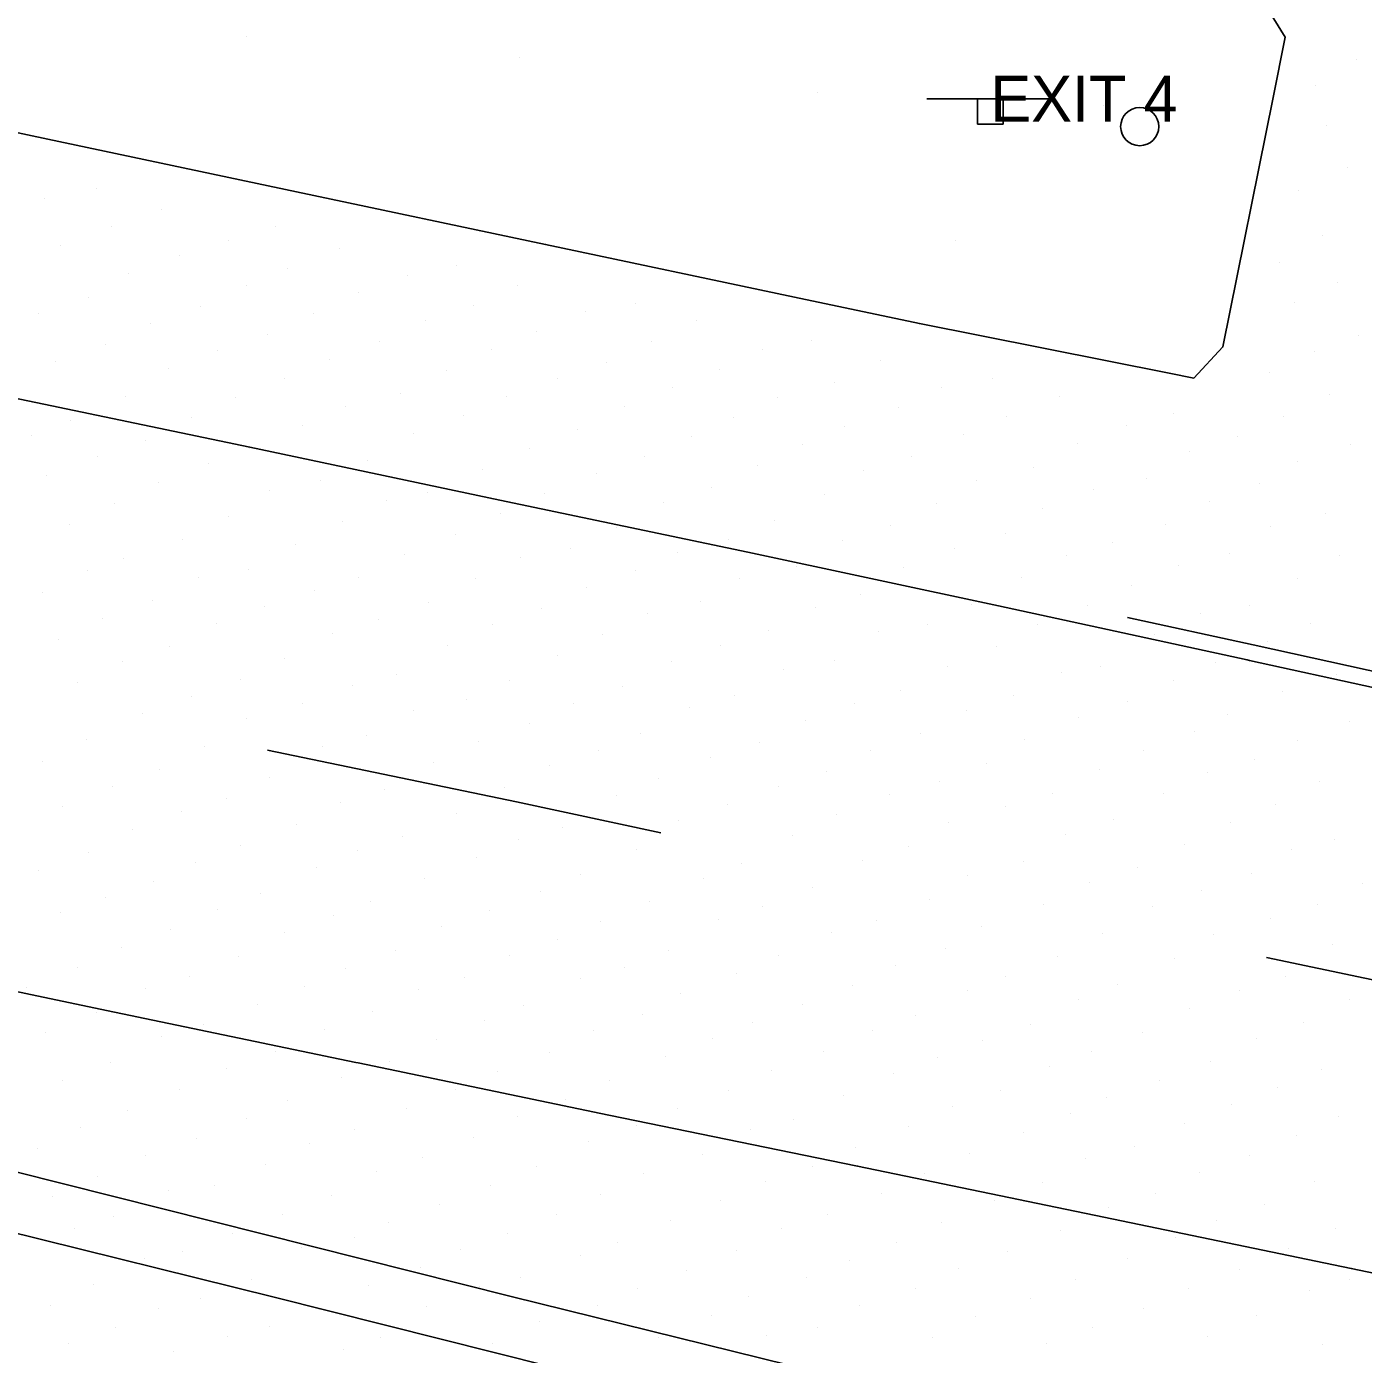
# Model space of a CAD drawing. Extents: x 1732346 to 1733076, y 467730 to 468633.
# Drawn here: x 1732773.5 to 1732826.1, y 468037.8 to 468090 of the extents above; entities that cross this region are included whole.
import ezdxf

# ---------------------------------------------------------------- set-up
doc = ezdxf.new("R2010")
doc.units = 0
for name, color, linetype in [('Default', 7, 'Continuous'), ('S_Ground_SpotElevation', 7, 'Continuous'), ('S_Guardrail_Beam', 7, 'Continuous'), ('S_Roadway_Edge_Pavement', 7, 'Continuous'), ('S_Roadway_Painted_Lines', 7, 'Continuous'), ('S_Text', 7, 'Continuous'), ('S_Traffic_Posts', 7, 'Continuous'), ('S_Traffic_Sign_SinglePost', 7, 'Continuous')]:
    doc.layers.add(name, color=color, linetype=linetype)

# ---------------------------------------------------------------- blocks, each defined once
blk = doc.blocks.new('POINT_DISPLAY')
at = {"layer": 'Default'}
blk.add_line((0, 0), (0, 0), dxfattribs=at)

msp = doc.modelspace()

# ---------------------------------------------------------------- linework, layer by layer
at = {"layer": 'S_Guardrail_Beam'}
for points in [[(1733057.134, 467971.295), (1733035.513, 467976.813), (1732996.091, 467986.731), (1732979.891, 467990.788), (1732924.503, 468005.981), (1732878.605, 468018.398), (1732839.517, 468028.474), (1732792.578, 468040.072), (1732765.198, 468046.962), (1732740.636, 468052.31), (1732695.156, 468062.036), (1732651.207, 468071.306), (1732593.235, 468083.607), (1732548.761, 468092.759), (1732525.66, 468097.849), (1732480.631, 468107.455), (1732450.278, 468113.819)], [(1732601.211, 468079.491), (1732624.681, 468074.488), (1732647.285, 468069.707), (1732677.097, 468063.407), (1732688.033, 468061.183), (1732704.968, 468057.509), (1732745.244, 468048.961), (1732757.76, 468046.26), (1732765.606, 468044.404), (1732772.588, 468042.691), (1732783.275, 468040.038), (1732800.615, 468035.672), (1732820.179, 468030.871), (1732839.038, 468026.193)]]:
    msp.add_lwpolyline(points, dxfattribs=at)
at = {"layer": 'S_Roadway_Edge_Pavement'}
msp.add_lwpolyline([(1732745.022, 468091.776), (1732754.805, 468089.704), (1732764.588, 468087.632), (1732774.371, 468085.56), (1732784.154, 468083.488), (1732793.937, 468081.416), (1732803.719, 468079.344), (1732808.631, 468078.304), (1732818.44, 468076.359), (1732819.413, 468076.166), (1732820.557, 468077.392), (1732822.529, 468087.196), (1732823.007, 468089.57), (1732821.659, 468091.736)], dxfattribs=at)
at = {"layer": 'S_Roadway_Painted_Lines'}
for points in [[(1732674.928, 468096.211), (1732684.719, 468094.102), (1732694.509, 468091.966), (1732704.231, 468089.834), (1732713.923, 468087.737), (1732723.729, 468085.628), (1732733.386, 468083.606), (1732743.244, 468081.582), (1732753.103, 468079.541), (1732762.798, 468077.529), (1732772.584, 468075.483), (1732772.711, 468075.456), (1732782.31, 468073.445), (1732792.144, 468071.365), (1732801.882, 468069.322), (1732811.732, 468067.208), (1732821.504, 468065.09), (1732821.605, 468065.069), (1732831.424, 468062.914)], [(1732669.338, 468074.084), (1732679.154, 468072.013), (1732688.927, 468069.949), (1732698.566, 468067.924), (1732708.376, 468065.853), (1732717.963, 468063.798), (1732727.768, 468061.722), (1732737.582, 468059.646), (1732747.326, 468057.582), (1732757.134, 468055.483), (1732766.913, 468053.366), (1732776.686, 468051.303), (1732786.474, 468049.265), (1732786.574, 468049.244), (1732796.428, 468047.189), (1732806.197, 468045.195), (1732815.879, 468043.181), (1732825.596, 468041.169), (1732835.331, 468039.133)], [(1732816.801, 468066.748), (1732821.738, 468065.678), (1732831.556, 468063.524), (1732841.335, 468061.437), (1732841.488, 468061.404), (1732851.348, 468059.327), (1732861.184, 468057.266), (1732870.85, 468055.293), (1732880.627, 468053.214), (1732890.392, 468051.101), (1732900.141, 468048.932), (1732909.856, 468046.816), (1732919.69, 468044.654), (1732928.671, 468042.737), (1732938.42, 468040.774), (1732947.936, 468038.748), (1732952.222, 468037.835)], [(1732783.004, 468061.533), (1732792.794, 468059.505), (1732798.466, 468058.296)], [(1732822.262, 468053.388), (1732832.047, 468051.334), (1732837.132, 468050.246)]]:
    msp.add_lwpolyline(points, dxfattribs=at)
at = {"layer": 'S_Traffic_Posts'}
msp.add_circle((1732817.284, 468086.048), 0.749, dxfattribs=at)
at = {"layer": 'S_Traffic_Sign_SinglePost'}
msp.add_line((1732808.92, 468087.145), (1732813.91, 468087.145), dxfattribs=at)
msp.add_lwpolyline([(1732810.916, 468087.145), (1732811.914, 468087.145), (1732811.914, 468086.147), (1732810.916, 468086.147)], close=True, dxfattribs=at)

# ---------------------------------------------------------------- block references
at = {"layer": 'S_Ground_SpotElevation'}
for p in [(1732782.169, 468089.575), (1732792.919, 468088.748), (1732825.81, 468088.678), (1732804.606, 468087.391), (1732824.182, 468087.646), (1732815.881, 468086.884), (1732824.634, 468086.108), (1732825.466, 468084.447), (1732774.263, 468083.23), (1732776.289, 468083.612), (1732823.517, 468083.553), (1732778.852, 468082.774), (1732776.89, 468082.113), (1732783.314, 468082.108), (1732781.47, 468081.576), (1732810.032, 468081.556), (1732824.476, 468081.759), (1732774.872, 468081.394), (1732785.851, 468081.24), (1732779.545, 468080.974), (1732790.423, 468080.599), (1732822.768, 468080.717), (1732777.54, 468080.282), (1732783.785, 468080.459), (1732788.525, 468080.188), (1732782.167, 468079.808), (1732786.58, 468079.533), (1732792.835, 468079.788), (1732825.047, 468079.91), (1732775.955, 468079.316), (1732780.372, 468078.958), (1732791.103, 468079.005), (1732797.487, 468079.093), (1732823.362, 468079.153), (1732774.023, 468078.686), (1732784.797, 468078.69), (1732789.206, 468078.415), (1732795.518, 468078.773), (1732799.867, 468078.435), (1732778.405, 468078.299), (1732793.594, 468078.004), (1732776.635, 468077.493), (1732783.024, 468077.862), (1732787.42, 468077.589), (1732798.112, 468077.618), (1732804.398, 468077.657), (1732825.887, 468077.823), (1732774.662, 468076.827), (1732781.039, 468077.262), (1732785.459, 468076.913), (1732791.813, 468077.271), (1732802.461, 468077.274), (1732807.107, 468076.87), (1732824.153, 468077.215), (1732779.129, 468076.546), (1732790.045, 468076.443), (1732796.339, 468076.795), (1732800.76, 468076.519), (1732822.395, 468076.395), (1732783.665, 468076.155), (1732794.403, 468076.151), (1732798.905, 468075.786), (1732805.308, 468075.999), (1732809.486, 468075.799), (1732811.487, 468076.139), (1732777.435, 468075.438), (1732781.738, 468075.403), (1732788.231, 468075.574), (1732792.404, 468075.431), (1732803.065, 468075.389), (1732814.116, 468075.449), (1732824.731, 468075.515), (1732786.073, 468075.057), (1732797.039, 468075.03), (1732807.798, 468074.997), (1732818.607, 468074.781), (1732775.28, 468074.494), (1732780.011, 468074.597), (1732784.371, 468074.301), (1732790.72, 468074.676), (1732801.329, 468074.614), (1732805.695, 468074.251), (1732812.038, 468074.67), (1732816.75, 468074.297), (1732822.931, 468074.652), (1732773.728, 468073.888), (1732778.22, 468073.705), (1732788.746, 468073.995), (1732795.209, 468074.147), (1732799.684, 468073.878), (1732810.349, 468073.93), (1732821.146, 468073.874), (1732782.295, 468073.399), (1732793.32, 468073.405), (1732804.021, 468073.539), (1732814.854, 468073.604), (1732819.235, 468073.267), (1732825.582, 468073.567), (1732776.326, 468073.08), (1732780.7, 468072.792), (1732786.92, 468072.917), (1732797.839, 468073.094), (1732802.28, 468072.739), (1732808.332, 468073.099), (1732813.129, 468072.631), (1732823.502, 468072.902), (1732774.324, 468072.333), (1732785.083, 468072.12), (1732791.443, 468072.581), (1732795.94, 468072.421), (1732806.442, 468072.523), (1732810.885, 468072.129), (1732817.552, 468072.229), (1732778.733, 468072.062), (1732783.09, 468071.76), (1732789.291, 468071.674), (1732793.908, 468071.646), (1732800.452, 468071.845), (1732804.912, 468071.595), (1732815.481, 468071.795), (1732821.991, 468072.016), (1732776.984, 468071.225), (1732787.695, 468071.372), (1732798.58, 468071.289), (1732809.307, 468071.253), (1732820.011, 468071.319), (1732781.495, 468070.742), (1732785.952, 468070.535), (1732792.166, 468070.823), (1732802.946, 468070.562), (1732813.449, 468071.037), (1732824.601, 468070.832), (1732775.224, 468070.391), (1732790.416, 468070.001), (1732796.719, 468070.276), (1732807.475, 468070.354), (1732812.015, 468070.065), (1732818.294, 468070.403), (1732822.442, 468070.32), (1732779.68, 468069.831), (1732784.116, 468069.608), (1732801.132, 468069.824), (1732805.59, 468069.774), (1732809.997, 468069.481), (1732816.223, 468069.711), (1732777.362, 468069.078), (1732788.405, 468069.245), (1732792.946, 468069.125), (1732794.9, 468069.448), (1732799.132, 468069.309), (1732814.406, 468069.177), (1732820.802, 468069.279), (1732825.13, 468069.206), (1732775.924, 468068.601), (1732782.265, 468068.652), (1732797.474, 468068.599), (1732803.804, 468068.74), (1732807.992, 468068.735), (1732818.795, 468068.783), (1732780.301, 468068.324), (1732786.569, 468068.316), (1732791.167, 468068.27), (1732795.55, 468067.95), (1732801.562, 468068.302), (1732812.639, 468068.345), (1732816.973, 468067.993), (1732823.474, 468068.283), (1732774.151, 468067.734), (1732778.482, 468067.417), (1732784.864, 468067.833), (1732800.043, 468067.387), (1732806.327, 468067.64), (1732782.886, 468067.172), (1732789.321, 468067.337), (1732793.781, 468067.127), (1732797.942, 468066.916), (1732804.532, 468067.15), (1732810.675, 468067.283), (1732815.22, 468067.225), (1732819.66, 468066.926), (1732821.604, 468067.206), (1732776.521, 468066.706), (1732781.001, 468066.535), (1732787.372, 468066.665), (1732791.869, 468066.495), (1732808.933, 468066.473), (1732813.255, 468066.483), (1732823.996, 468066.513), (1732774.795, 468065.89), (1732785.548, 468066.117), (1732796.187, 468066.098), (1732802.697, 468066.247), (1732807.002, 468066.199), (1732817.876, 468066.092), (1732822.318, 468065.798), (1732779.153, 468065.599), (1732790.096, 468065.642), (1732800.807, 468065.656), (1732811.641, 468065.62), (1732777.303, 468065.022), (1732783.679, 468065.145), (1732794.416, 468065.246), (1732798.887, 468065.025), (1732805.283, 468065.054), (1732809.734, 468064.809), (1732815.751, 468064.845), (1732820.261, 468065.001), (1732781.932, 468064.308), (1732788.086, 468064.52), (1732792.51, 468064.267), (1732803.292, 468064.709), (1732814.201, 468064.589), (1732818.63, 468064.276), (1732825.001, 468064.5), (1732775.558, 468064.193), (1732786.332, 468064.063), (1732796.975, 468064.041), (1732801.373, 468063.707), (1732807.885, 468063.882), (1732822.882, 468063.828), (1732780.019, 468063.646), (1732784.369, 468063.37), (1732790.834, 468063.539), (1732795.018, 468063.365), (1732799.573, 468063.215), (1732806.081, 468063.377), (1732812.333, 468063.672), (1732816.811, 468063.461), (1732778.107, 468062.999), (1732782.182, 468062.77), (1732788.759, 468063.095), (1732804.135, 468062.72), (1732810.488, 468063.11), (1732814.886, 468062.813), (1732820.717, 468062.923), (1732825.531, 468062.679), (1732786.894, 468062.135), (1732793.293, 468062.574), (1732797.658, 468062.212), (1732808.669, 468062.21), (1732819.433, 468062.265), (1732775.897, 468061.947), (1732780.532, 468061.665), (1732785.159, 468061.686), (1732791.315, 468061.869), (1732802.334, 468061.858), (1732812.748, 468061.946), (1732823.48, 468061.915), (1732774.155, 468061.084), (1732796.002, 468061.528), (1732800.431, 468061.237), (1732806.704, 468061.514), (1732817.422, 468061.546), (1732821.795, 468061.182), (1732778.777, 468060.767), (1732789.549, 468061.039), (1732794.109, 468060.927), (1732804.959, 468060.715), (1732811.247, 468061.029), (1732815.719, 468060.788), (1732819.961, 468060.659), (1732776.927, 468060.126), (1732783.106, 468060.475), (1732792.304, 468060.057), (1732798.365, 468060.442), (1732803.078, 468060.122), (1732809.417, 468060.304), (1732824.342, 468060.292), (1732781.379, 468059.625), (1732787.609, 468059.979), (1732796.735, 468059.768), (1732807.439, 468059.788), (1732813.866, 468059.846), (1732818.22, 468059.855), (1732774.938, 468059.342), (1732779.644, 468059.137), (1732785.862, 468059.489), (1732790.435, 468059.051), (1732801.079, 468059.4), (1732805.378, 468059.003), (1732812.002, 468059.324), (1732822.616, 468059.421), (1732784.133, 468058.637), (1732794.613, 468058.514), (1732799.148, 468058.756), (1732809.759, 468058.693), (1732816.257, 468058.813), (1732820.868, 468058.714), (1732777.712, 468058.412), (1732788.32, 468058.144), (1732792.868, 468058.038), (1732803.638, 468058.19), (1732814.373, 468058.231), (1732824.951, 468058.023), (1732775.963, 468057.532), (1732781.941, 468057.789), (1732786.534, 468057.603), (1732797.492, 468057.638), (1732808.218, 468057.748), (1732819.045, 468057.826), (1732823.248, 468057.645), (1732780.186, 468057.127), (1732784.934, 468056.918), (1732791.228, 468057.304), (1732801.639, 468057.081), (1732806.378, 468057.21), (1732812.728, 468057.174), (1732817.206, 468056.926), (1732774.023, 468056.801), (1732778.526, 468056.369), (1732789.195, 468056.503), (1732795.313, 468056.66), (1732800.142, 468056.508), (1732810.529, 468056.617), (1732815.317, 468056.343), (1732821.679, 468056.673), (1732782.729, 468055.921), (1732793.726, 468055.989), (1732804.44, 468056.152), (1732819.725, 468056.011), (1732826.056, 468056.312), (1732776.655, 468055.74), (1732781.031, 468055.296), (1732787.066, 468055.578), (1732798.028, 468055.605), (1732802.453, 468055.388), (1732809.005, 468055.683), (1732813.5, 468055.467), (1732817.802, 468055.388), (1732824.265, 468055.457), (1732774.87, 468055.17), (1732785.603, 468055.05), (1732791.72, 468055.219), (1732796.112, 468054.823), (1732800.713, 468054.887), (1732806.922, 468054.835), (1732822.411, 468054.918), (1732779.179, 468054.485), (1732783.684, 468054.367), (1732789.84, 468054.594), (1732805.187, 468054.358), (1732811.087, 468054.627), (1732815.842, 468054.333), (1732820.178, 468054.31), (1732777.269, 468053.773), (1732794.389, 468054.112), (1732809.635, 468053.746), (1732824.851, 468053.917), (1732781.874, 468053.442), (1732788.023, 468053.671), (1732792.528, 468053.482), (1732798.757, 468053.682), (1732803.082, 468053.477), (1732814.043, 468053.444), (1732818.653, 468053.366), (1732775.535, 468052.984), (1732786.063, 468052.952), (1732797.055, 468053.009), (1732801.443, 468052.748), (1732807.704, 468053.072), (1732773.556, 468052.199), (1732778.218, 468052.174), (1732779.928, 468052.626), (1732784.473, 468052.268), (1732788.957, 468052.138), (1732790.742, 468052.609), (1732795.32, 468052.548), (1732806.016, 468052.303), (1732812.013, 468052.653), (1732816.419, 468052.343), (1732823.033, 468052.655), (1732799.225, 468051.96), (1732810.512, 468052.091), (1732814.864, 468051.721), (1732821.202, 468052.091), (1732825.541, 468051.738), (1732776.301, 468051.211), (1732782.63, 468051.53), (1732787.138, 468051.272), (1732793.075, 468051.503), (1732797.73, 468051.155), (1732804.034, 468051.562), (1732808.482, 468051.104), (1732819.251, 468051.388), (1732780.486, 468050.742), (1732791.538, 468050.923), (1732802.065, 468050.835), (1732813.012, 468050.771), (1732823.741, 468050.828), (1732774.3, 468050.447), (1732778.849, 468050.279), (1732785.257, 468050.543), (1732789.639, 468050.157), (1732795.837, 468050.51), (1732800.504, 468050.195), (1732806.788, 468050.532), (1732811.114, 468050.136), (1732817.381, 468050.425), (1732821.87, 468050.215), (1732783.318, 468049.68), (1732794.075, 468049.663), (1732804.856, 468049.698), (1732815.408, 468049.707), (1732776.844, 468049.253), (1732781.4, 468049.043), (1732787.798, 468049.299), (1732798.633, 468049.484), (1732809.331, 468049.446), (1732813.749, 468049.118), (1732820.071, 468049.322), (1732774.941, 468048.541), (1732785.936, 468048.688), (1732792.063, 468048.922), (1732796.438, 468048.552), (1732802.821, 468048.938), (1732807.598, 468048.818), (1732818.052, 468048.55), (1732824.425, 468048.982), (1732779.544, 468048.185), (1732790.405, 468048.213), (1732801.109, 468048.177), (1732805.64, 468047.975), (1732811.831, 468048.154), (1732822.698, 468048.278), (1732783.814, 468047.786), (1732788.467, 468047.449), (1732794.731, 468047.792), (1732799.104, 468047.442), (1732809.943, 468047.544), (1732815.97, 468047.874), (1732820.886, 468047.619), (1732777.52, 468047.358), (1732782.174, 468047.064), (1732792.826, 468047.133), (1732803.665, 468047.013), (1732814.557, 468047.249), (1732825.116, 468047.156), (1732775.652, 468046.702), (1732786.431, 468046.615), (1732797.495, 468046.791), (1732801.978, 468046.629), (1732808.182, 468046.736), (1732812.712, 468046.52), (1732819.039, 468046.852), (1732823.459, 468046.413), (1732773.989, 468045.896), (1732780.203, 468046.291), (1732784.645, 468046.069), (1732791.105, 468046.313), (1732795.605, 468046.156), (1732806.111, 468045.939), (1732817.064, 468045.956), (1732778.224, 468045.589), (1732789.116, 468045.546), (1732800.108, 468045.661), (1732810.612, 468045.691), (1732815.151, 468045.502), (1732821.587, 468045.611), (1732782.935, 468045.236), (1732787.301, 468044.969), (1732793.566, 468045.159), (1732797.801, 468044.904), (1732804.417, 468045.191), (1732808.818, 468044.893), (1732819.637, 468044.926), (1732776.33, 468044.779), (1732780.931, 468044.435), (1732791.763, 468044.421), (1732802.56, 468044.6), (1732813.464, 468044.534), (1732824.153, 468044.599), (1732774.54, 468044.005), (1732779.113, 468044.221), (1732785.521, 468044.049), (1732796.082, 468044.084), (1732800.817, 468043.829), (1732807.14, 468044.126), (1732811.587, 468043.83), (1732817.887, 468044.125), (1732776.946, 468043.225), (1732783.594, 468043.308), (1732789.772, 468043.695), (1732794.36, 468043.298), (1732805.03, 468043.298), (1732816.067, 468043.571), (1732822.185, 468043.697), (1732775.42, 468042.725), (1732787.781, 468042.991), (1732798.844, 468043.069), (1732803.195, 468042.738), (1732809.48, 468042.992), (1732820.291, 468043.065), (1732824.994, 468042.723), (1732781.63, 468042.537), (1732786.43, 468042.395), (1732792.441, 468042.537), (1732796.767, 468042.204), (1732807.713, 468042.191), (1732814.183, 468042.643), (1732818.683, 468042.398), (1732779.678, 468041.833), (1732784.356, 468042.003), (1732790.598, 468041.928), (1732795.321, 468041.661), (1732801.455, 468041.872), (1732812.1, 468041.848), (1732823.116, 468041.954), (1732778.166, 468041.568), (1732789.007, 468041.215), (1732805.888, 468041.464), (1732810.166, 468041.184), (1732816.804, 468041.579), (1732821.193, 468041.13), (1732782.387, 468040.744), (1732792.936, 468040.804), (1732799.474, 468041.093), (1732804.18, 468040.794), (1732814.775, 468040.721), (1732825.547, 468040.753), (1732776.177, 468040.547), (1732786.983, 468040.498), (1732791.338, 468040.468), (1732797.56, 468040.4), (1732801.91, 468040.076), (1732808.478, 468040.382), (1732819.197, 468040.376), (1732823.957, 468040.298), (1732774.479, 468039.732), (1732778.737, 468039.608), (1732780.386, 468039.998), (1732785.026, 468039.558), (1732789.242, 468039.686), (1732795.974, 468039.701), (1732806.261, 468039.726), (1732812.979, 468039.978), (1732817.42, 468039.607), (1732793.695, 468039.072), (1732800.454, 468039.314), (1732810.846, 468039.284), (1732821.88, 468039.315), (1732777.048, 468038.85), (1732781.444, 468038.493), (1732783.105, 468038.881), (1732802.612, 468038.53), (1732804.605, 468038.861), (1732815.44, 468038.861), (1732819.948, 468038.505), (1732775.204, 468038.231), (1732785.982, 468037.964), (1732787.453, 468038.466), (1732791.864, 468038.215), (1732798.384, 468038.47), (1732809.141, 468038.464), (1732813.604, 468038.237), (1732824.488, 468038.163), (1732779.299, 468037.915)]:
    msp.add_blockref('POINT_DISPLAY', p, dxfattribs=at)

# ---------------------------------------------------------------- texts
at = {"layer": 'S_Text'}
msp.add_text('EXIT 4', height=1.8, dxfattribs=at).set_placement((1732811.415, 468086.245))

doc.saveas('drawing.dxf')
